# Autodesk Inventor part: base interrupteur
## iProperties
Author: Administrateur
Created: 2001-04
Part Number: base interrupteur
Material: Par défaut
Document SubType Name: Modélisation
Designer: Administrateur
Control State: 0
Master: False
Checked Out: False
PropertySet Name: Design Tracking Control
Shininess: 86.0
PropertySet Name: _Private Model Information
Length Units: 11269
Angle Units: 11283
Time Units: 11279
Mass Units: 11290
Length Display Precision: 3
Angle Display Precision: 2
Compacted: False
Density: 0.0
Volumn: 0.0
Area: 0.0
PropertySet Name: Model Information
